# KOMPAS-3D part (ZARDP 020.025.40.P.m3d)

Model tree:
1. Плоскость XY
2. Плоскость ZX
3. Плоскость ZY
4. Ось X
5. Ось Y
6. Ось Z
7. Начало координат
8. Смещенная плоскость:2
     Расстояние = 60
9. Булева операция:1
10. Булева операция:2
